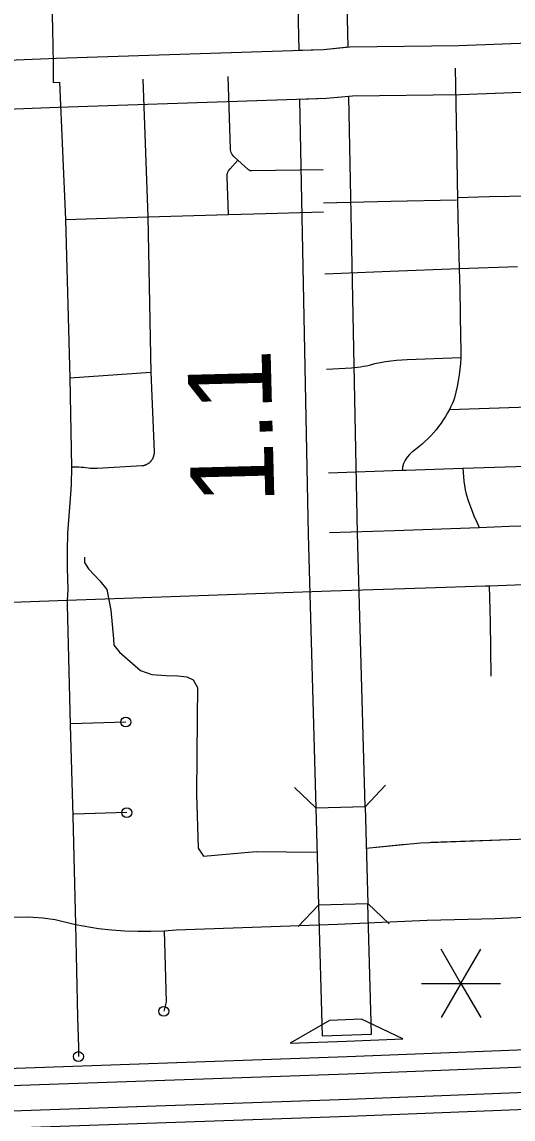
# Model space of a CAD drawing. Extents: x 309348 to 309445, y 336383 to 336484.
# Drawn here: x 309350.787 to 309351.284, y 336397.601 to 336398.714 of the extents above; entities that cross this region are included whole.
import ezdxf

# ---------------------------------------------------------------- set-up
doc = ezdxf.new("R2010")
doc.units = 0
doc.layers.add('R_Annotation', color=7, linetype='Continuous')

msp = doc.modelspace()

# ---------------------------------------------------------------- linework, layer by layer
at = {"layer": 'R_Annotation'}
for p, q in [((309351.2317, 336397.7385), (309351.2117, 336397.7732)), ((309351.2317, 336397.7385), (309351.2517, 336397.7732)), ((309351.1917, 336397.7385), (309351.2317, 336397.7385)), ((309351.2317, 336397.7385), (309351.2117, 336397.7038)), ((309351.2317, 336397.7385), (309351.2717, 336397.7385)), ((309351.2317, 336397.7385), (309351.2517, 336397.7038)), ((309351.0986, 336397.701), (309351.0586, 336397.6779)), ((309351.131, 336397.7022), (309351.0986, 336397.701)), ((309351.1726, 336397.6822), (309351.131, 336397.7022)), ((309351.0586, 336397.6779), (309351.1156, 336397.68)), ((309351.1156, 336397.68), (309351.1726, 336397.6822))]:
    msp.add_line(p, q, dxfattribs=at)
for points in [[(309351.0564, 336399.154), (309351.0674, 336398.6853), (309351.0922, 336398.6862), (309351.1174, 336398.6886)], [(309351.1174, 336398.6886), (309351.1064, 336399.1548)], [(309350.8158, 336398.7878), (309350.8177, 336398.7067), (309350.8184, 336398.6714), (309350.8185, 336398.6527)], [(309349.8623, 336398.6397), (309350.0367, 336398.6445), (309350.293, 336398.6565), (309350.526, 336398.6654), (309350.5648, 336398.6692), (309350.6905, 336398.6719), (309350.8216, 336398.6772), (309351.0922, 336398.6862), (309351.1191, 336398.6887), (309351.2294, 336398.6901), (309351.5664, 336398.7029)], [(309351.2258, 336398.6672), (309351.2271, 336398.5946)], [(309351.5674, 336398.6529), (309351.2307, 336398.6401), (309351.1218, 336398.6387), (309351.0953, 336398.6362), (309350.8234, 336398.6272), (309350.692, 336398.622), (309350.5678, 336398.6192), (309350.5293, 336398.6155), (309350.2951, 336398.6066), (309350.0385, 336398.5945), (309349.8382, 336398.589)], [(309350.8185, 336398.6527), (309350.8247, 336398.6528)], [(309350.8247, 336398.6528), (309350.8307, 336398.5136)], [(309350.9092, 336398.6558), (309350.9144, 336398.5162)], [(309351.0919, 336398.5639), (309351.0197, 336398.5629), (309351.0188, 336398.5629), (309351.0179, 336398.5631), (309351.0171, 336398.5635), (309351.0163, 336398.564), (309351.0161, 336398.5642), (309351.0055, 336398.5737), (309351.002, 336398.5769), (309351.0015, 336398.5774), (309350.9999, 336398.5794), (309350.9988, 336398.5817), (309350.9982, 336398.5842), (309350.9981, 336398.5854), (309350.9956, 336398.6587)], [(309351.1345, 336397.9179), (309351.1269, 336398.1951), (309351.1181, 336398.6384), (309351.0953, 336398.6362), (309351.0681, 336398.6353)], [(309351.0681, 336398.6353), (309351.0769, 336398.1939), (309351.0845, 336397.9165), (309351.1345, 336397.9179)], [(309351.2271, 336398.5946), (309351.2282, 336398.5334)], [(309350.9961, 336398.5186), (309350.9947, 336398.557), (309350.9948, 336398.5584), (309350.9952, 336398.5608), (309350.9962, 336398.563), (309350.9976, 336398.565), (309351.0055, 336398.5737)], [(309351.2282, 336398.5359), (309351.2601, 336398.5368), (309351.3223, 336398.538), (309351.3584, 336398.5395), (309351.3888, 336398.5411), (309351.413, 336398.5419), (309351.4551, 336398.5436), (309351.5127, 336398.5455), (309351.5467, 336398.5466), (309351.5942, 336398.5483)], [(309351.0925, 336398.5306), (309351.1606, 336398.532), (309351.2272, 336398.5334)], [(309351.2282, 336398.5334), (309351.2285, 336398.5154), (309351.23, 336398.464)], [(309350.9144, 336398.5162), (309350.9961, 336398.5186), (309351.0218, 336398.5193), (309351.0925, 336398.5212)], [(309350.8307, 336398.5136), (309350.9144, 336398.5162)], [(309350.8307, 336398.5136), (309350.8351, 336398.3526)], [(309350.9144, 336398.5162), (309350.9175, 336398.3585)], [(309351.0936, 336398.4583), (309351.16, 336398.4612), (309351.23, 336398.464)], [(309351.23, 336398.464), (309351.2891, 336398.466)], [(309351.23, 336398.464), (309351.2306, 336398.4423), (309351.2313, 336398.3941), (309351.2315, 336398.3815), (309351.2315, 336398.3775), (309351.2314, 336398.3736)], [(309351.0953, 336398.3618), (309351.1208, 336398.3631), (309351.1238, 336398.3633), (309351.1269, 336398.3636), (309351.1299, 336398.3641), (309351.133, 336398.3646), (309351.136, 336398.3652), (309351.1389, 336398.3659), (309351.1443, 336398.3673), (309351.1498, 336398.3684), (309351.1552, 336398.3694), (309351.1607, 336398.3702), (309351.1663, 336398.3709), (309351.1718, 336398.3713), (309351.1773, 336398.3716), (309351.2314, 336398.3736)], [(309351.2314, 336398.3736), (309351.2311, 336398.3676), (309351.2306, 336398.3617), (309351.2299, 336398.3558), (309351.229, 336398.35), (309351.2279, 336398.3441), (309351.2266, 336398.3383), (309351.2251, 336398.3326), (309351.224, 336398.3296), (309351.2227, 336398.3267), (309351.2214, 336398.3238), (309351.22, 336398.3209)], [(309350.9175, 336398.3585), (309350.8351, 336398.3526)], [(309350.8351, 336398.3526), (309350.837, 336398.2622)], [(309350.9175, 336398.3585), (309350.9206, 336398.2778), (309350.9206, 336398.2773), (309350.9206, 336398.2768), (309350.9206, 336398.2764), (309350.9206, 336398.2759), (309350.9205, 336398.2754), (309350.9204, 336398.275), (309350.9203, 336398.2745), (309350.9202, 336398.274), (309350.9201, 336398.2736), (309350.92, 336398.2731), (309350.9198, 336398.2727), (309350.9197, 336398.2722), (309350.9195, 336398.2718), (309350.9193, 336398.2713), (309350.9191, 336398.2709), (309350.9189, 336398.2705), (309350.9186, 336398.2701), (309350.9184, 336398.2697), (309350.9181, 336398.2693), (309350.9178, 336398.2689), (309350.9175, 336398.2685), (309350.9172, 336398.2682), (309350.9169, 336398.2678), (309350.9166, 336398.2675), (309350.9162, 336398.2672), (309350.9159, 336398.2668), (309350.9155, 336398.2665), (309350.9151, 336398.2662), (309350.9147, 336398.266), (309350.9144, 336398.2657), (309350.914, 336398.2654), (309350.9135, 336398.2652), (309350.9131, 336398.265), (309350.9127, 336398.2648), (309350.9123, 336398.2646), (309350.9118, 336398.2644), (309350.9114, 336398.2642), (309350.9109, 336398.2641), (309350.9105, 336398.264), (309350.91, 336398.2638), (309350.9095, 336398.2637), (309350.9091, 336398.2637), (309350.9086, 336398.2636), (309350.8628, 336398.2611), (309350.8605, 336398.261), (309350.8583, 336398.261), (309350.856, 336398.2611), (309350.8538, 336398.2612), (309350.8492, 336398.2618), (309350.8467, 336398.2621), (309350.8443, 336398.2622), (309350.8419, 336398.2623), (309350.8394, 336398.2623), (309350.837, 336398.2622)], [(309351.22, 336398.3209), (309351.218, 336398.3173), (309351.216, 336398.3137), (309351.2138, 336398.3102), (309351.2115, 336398.3068), (309351.209, 336398.3035), (309351.2065, 336398.3002), (309351.2038, 336398.2971), (309351.2011, 336398.294), (309351.1982, 336398.2911), (309351.1952, 336398.2882), (309351.1922, 336398.2855), (309351.189, 336398.2828), (309351.1857, 336398.2803)], [(309351.22, 336398.3209), (309351.3605, 336398.3254)], [(309351.1857, 336398.2803), (309351.1826, 336398.278), (309351.1823, 336398.2778), (309351.1794, 336398.2753), (309351.177, 336398.2725), (309351.175, 336398.2693), (309351.1735, 336398.2659), (309351.1725, 336398.2623), (309351.1721, 336398.2591)], [(309351.2337, 336398.2612), (309351.3089, 336398.2637), (309351.3629, 336398.2654)], [(309350.837, 336398.2622), (309350.8365, 336398.2446), (309350.8359, 336398.2349), (309350.8329, 336398.1954), (309350.8324, 336398.1777), (309350.8325, 336398.1601), (309350.8331, 336398.138), (309350.8326, 336398.1272)], [(309351.0974, 336398.2566), (309351.1721, 336398.2591)], [(309351.1721, 336398.2591), (309351.1761, 336398.2592), (309351.2337, 336398.2612)], [(309351.2337, 336398.2612), (309351.2339, 336398.2568), (309351.2342, 336398.2524), (309351.2347, 336398.248), (309351.2353, 336398.2436), (309351.236, 336398.2393), (309351.2369, 336398.2349), (309351.2393, 336398.2275), (309351.242, 336398.2202), (309351.2448, 336398.213), (309351.248, 336398.2059), (309351.2502, 336398.2012)], [(309351.0985, 336398.196), (309351.1642, 336398.1982), (309351.2502, 336398.2012)], [(309351.2502, 336398.2012), (309351.2805, 336398.2023), (309351.3641, 336398.2048)], [(309350.8502, 336398.171), (309350.8502, 336398.1657), (309350.8541, 336398.1592), (309350.8655, 336398.1469), (309350.8729, 336398.1382), (309350.8768, 336398.1171), (309350.8794, 336398.088), (309350.8797, 336398.0818), (309350.8855, 336398.0747), (309350.9069, 336398.0559), (309350.9182, 336398.052), (309350.9328, 336398.051), (309350.9448, 336398.0507), (309350.9539, 336398.0494), (309350.9603, 336398.0465), (309350.9646, 336398.0387), (309350.9642, 336398.008), (309350.9636, 336397.9305), (309350.9652, 336397.8758), (309350.9707, 336397.8677), (309351.024, 336397.8722), (309351.0857, 336397.8718)], [(309351.0999, 336398.1368), (309351.1956, 336398.1398)], [(309351.1956, 336398.1398), (309351.2561, 336398.1418), (309351.2603, 336398.1419)], [(309351.2603, 336398.1419), (309351.3303, 336398.1445)], [(309351.2603, 336398.1419), (309351.2612, 336398.1055), (309351.2618, 336398.0504)], [(309350.8326, 336398.1272), (309351.0999, 336398.1368)], [(309350.5709, 336398.118), (309350.8326, 336398.1272)], [(309350.8326, 336398.1272), (309350.8324, 336398.1228), (309350.8355, 336398.0009)], [(309350.8355, 336398.0009), (309350.8384, 336397.9083)], [(309350.892, 336398.0037), (309350.8363, 336398.0018)], [(309351.1552, 336397.9395), (309351.1345, 336397.9177)], [(309351.0845, 336397.9165), (309351.0628, 336397.9372)], [(309351.1345, 336397.9179), (309351.1372, 336397.8194)], [(309350.8384, 336397.9083), (309350.8411, 336397.7982)], [(309350.893, 336397.9118), (309350.8392, 336397.9101)], [(309351.0845, 336397.9165), (309351.0872, 336397.818)], [(309351.1357, 336397.8757), (309351.1905, 336397.8813), (309351.317, 336397.8859)], [(309351.2014, 336397.8817), (309351.2806, 336397.8846)], [(309351.1357, 336397.8757), (309351.1751, 336397.8797)], [(309351.0666, 336397.7962), (309351.0872, 336397.818)], [(309351.1409, 336397.6869), (309351.1372, 336397.8194), (309351.0872, 336397.818)], [(309351.0872, 336397.818), (309351.0909, 336397.6855), (309351.1409, 336397.6869)], [(309351.1372, 336397.8195), (309351.159, 336397.7989)], [(309350.5759, 336397.7991), (309350.6419, 336397.8015), (309350.7016, 336397.8037), (309350.7727, 336397.8059), (309350.7934, 336397.8061), (309350.8079, 336397.805), (309350.8203, 336397.8034), (309350.8411, 336397.7982)], [(309351.1067, 336397.7986), (309351.1974, 336397.8028), (309351.2663, 336397.8045), (309351.3433, 336397.8079), (309351.3772, 336397.8088)], [(309350.8411, 336397.7982), (309350.8419, 336397.7517), (309350.843, 336397.7043), (309350.8441, 336397.6736), (309350.844, 336397.6643)], [(309350.8411, 336397.7982), (309350.8644, 336397.7941), (309350.8776, 336397.7928), (309350.8909, 336397.7919), (309350.9041, 336397.7915), (309350.9174, 336397.7915), (309350.9307, 336397.792)], [(309350.9307, 336397.792), (309350.943, 336397.7929), (309351.1067, 336397.7986)], [(309350.9307, 336397.792), (309350.9319, 336397.7564), (309350.933, 336397.7197), (309350.9305, 336397.7102)], [(309352.6868, 336397.729), (309352.1859, 336397.7061), (309351.1163, 336397.6639), (309350.5792, 336397.645), (309349.6821, 336397.6116), (309349.5744, 336397.6063), (309349.1696, 336397.5933), (309349.0937, 336397.5896), (309348.838, 336397.5802), (309348.6889, 336397.576), (309348.5061, 336397.574), (309348.4455, 336397.5778), (309348.4023, 336397.5837), (309348.3471, 336397.5936), (309348.2597, 336397.6131), (309348.2175, 336397.6264), (309348.1904, 336397.6364), (309348.1261, 336397.6629)], [(309348.1138, 336397.6496), (309348.1842, 336397.6206), (309348.212, 336397.6103), (309348.2553, 336397.5967), (309348.3438, 336397.5769), (309348.3996, 336397.567), (309348.4438, 336397.5608), (309348.5057, 336397.557), (309348.6892, 336397.559), (309348.8386, 336397.5632), (309349.0944, 336397.5726), (309349.1703, 336397.5763), (309349.5751, 336397.5893), (309349.6829, 336397.5946), (309350.5798, 336397.6281), (309351.1169, 336397.6469), (309352.1866, 336397.6891), (309352.6878, 336397.712)], [(309352.6892, 336397.6861), (309352.1877, 336397.6631), (309351.1179, 336397.6209), (309350.5807, 336397.6021), (309349.684, 336397.5686), (309349.5761, 336397.5633), (309349.1714, 336397.5504), (309349.0955, 336397.5466), (309348.8394, 336397.5372), (309348.6897, 336397.533), (309348.505, 336397.5309), (309348.4412, 336397.5349), (309348.3955, 336397.5413), (309348.3387, 336397.5514), (309348.2486, 336397.5715), (309348.2036, 336397.5857), (309348.1748, 336397.5963), (309348.0954, 336397.6291)], [(309348.0833, 336397.616), (309348.0912, 336397.6124), (309348.1686, 336397.5805), (309348.1981, 336397.5696), (309348.2442, 336397.5551), (309348.3353, 336397.5348), (309348.3929, 336397.5245), (309348.4395, 336397.518), (309348.5046, 336397.5139), (309348.69, 336397.516), (309348.8399, 336397.5202), (309349.0962, 336397.5296), (309349.1721, 336397.5334), (309349.5768, 336397.5463), (309349.6847, 336397.5516), (309350.5813, 336397.5851), (309351.1185, 336397.604), (309352.1884, 336397.6461), (309352.6902, 336397.6691)]]:
    msp.add_lwpolyline(points, dxfattribs=at)
for centre in [(309350.892, 336398.0037), (309350.893, 336397.9118), (309350.9305, 336397.7102), (309350.844, 336397.6643)]:
    msp.add_circle(centre, 0.005, dxfattribs=at)

# ---------------------------------------------------------------- texts
msp.add_text('1.1', height=0.08451, rotation=91.473, dxfattribs=at).set_placement((309351.0427, 336398.2255))

doc.saveas('drawing.dxf')
